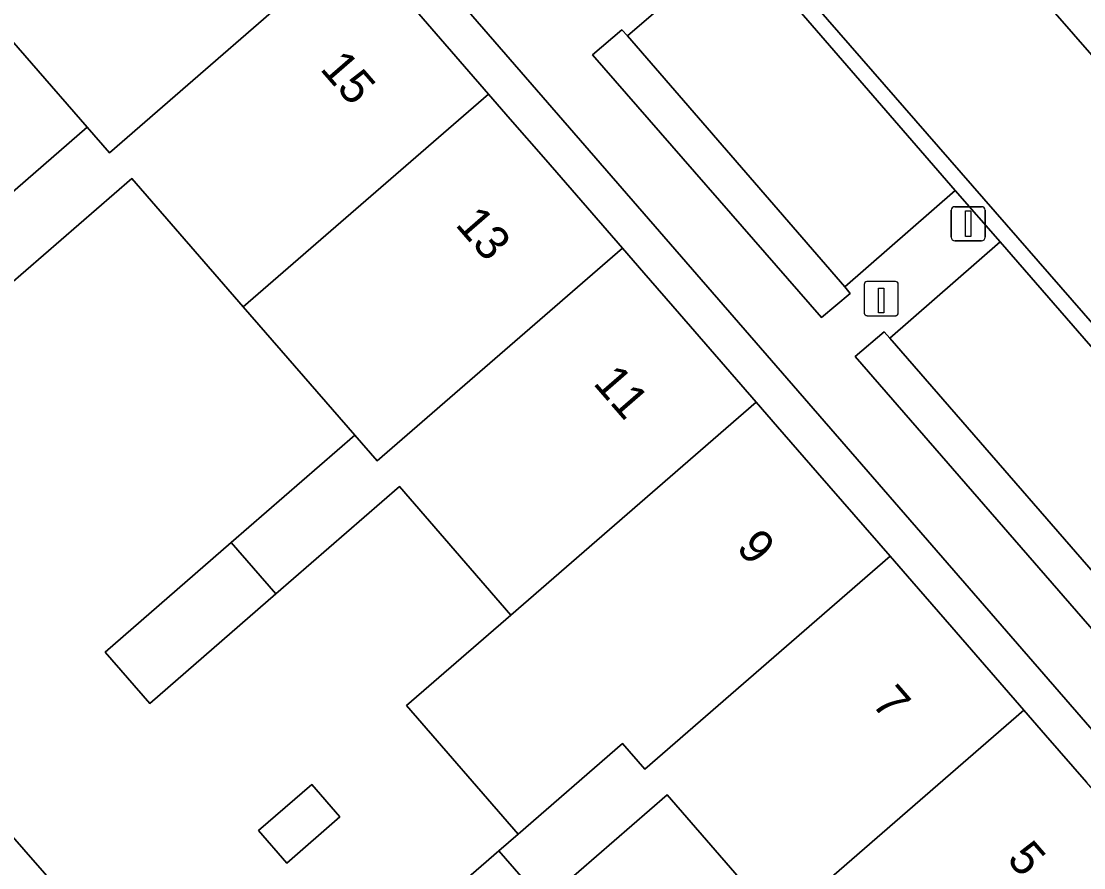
# Model space of a CAD drawing. Extents: x 155887 to 156869, y 383880 to 384678.
# Drawn here: x 156668 to 156699.23, y 384051.97 to 384076.85 of the extents above; entities that cross this region are included whole.
import ezdxf

# ---------------------------------------------------------------- set-up
doc = ezdxf.new("R2010")
doc.units = 0
for name, color, linetype in [('IMGEO_Erf', 7, 'Continuous'), ('IMGEO_Groenvoorziening', 7, 'Continuous'), ('IMGEO_Haag', 7, 'Continuous'), ('IMGEO_Laadpaal', 7, 'Continuous'), ('IMGEO_Lichtmast', 7, 'Continuous'), ('IMGEO_Pand', 7, 'Continuous'), ('IMGEO_Pand_nummerreeks', 7, 'Continuous'), ('IMGEO_Parkeervlak_open', 7, 'Continuous'), ('IMGEO_Rijbaan_lokaal_gesloten', 7, 'Continuous'), ('IMGEO_Rijbaan_lokaal_open', 7, 'Continuous'), ('IMGEO_Voetpad_open', 7, 'Continuous')]:
    doc.layers.add(name, color=color, linetype=linetype)

msp = doc.modelspace()

# ---------------------------------------------------------------- linework, layer by layer
at = {"layer": 'IMGEO_Erf'}
for points in [[(156702.45, 384052.606), (156666.669, 384093.809)], [(156666.303, 384070.582), (156669.934, 384073.737), (156666.655, 384077.511)], [(156679.36, 384077.444), (156681.735, 384074.71), (156682.374, 384073.976), (156683.419, 384072.773), (156685.67, 384070.182), (156686.301, 384069.455), (156687.351, 384068.248), (156689.605, 384065.653), (156690.235, 384064.928), (156691.407, 384063.579), (156693.539, 384061.125), (156694.178, 384060.389), (156695.355, 384059.035), (156697.474, 384056.596), (156698.108, 384055.866), (156699.314, 384054.479)], [(156646.945, 384076.691), (156671.041, 384049.103)], [(156678.337, 384049.248), (156682.042, 384052.467), (156682.604, 384052.955), (156679.326, 384056.734), (156682.394, 384059.396), (156679.115, 384063.17), (156675.484, 384060.015), (156671.779, 384056.795), (156670.467, 384058.305), (156674.173, 384061.524), (156677.804, 384064.679), (156674.525, 384068.453), (156671.246, 384072.227), (156667.615, 384069.072)], [(156690.262, 384050.338), (156686.985, 384054.112), (156683.354, 384050.957)]]:
    msp.add_lwpolyline(points, dxfattribs=at)
msp.add_lwpolyline([(156675.802, 384052.106), (156674.974, 384053.058), (156676.537, 384054.416), (156677.365, 384053.464)], close=True, dxfattribs=at)
at = {"layer": 'IMGEO_Groenvoorziening'}
for points in [[(156685.823, 384076.419), (156685.653, 384076.598), (156684.796, 384075.865), (156691.528, 384068.14), (156692.365, 384068.849), (156692.215, 384069.042)], [(156693.531, 384067.538), (156693.363, 384067.725), (156692.513, 384066.999), (156703.906, 384053.898), (156704.744, 384054.644), (156701.662, 384058.188)]]:
    msp.add_lwpolyline(points, close=True, dxfattribs=at)
at = {"layer": 'IMGEO_Haag'}
for points in [[(156692.215, 384069.042), (156685.823, 384076.419), (156685.653, 384076.598), (156684.796, 384075.865), (156691.528, 384068.14), (156692.365, 384068.849)], [(156701.662, 384058.188), (156693.531, 384067.538), (156693.363, 384067.725), (156692.513, 384066.999), (156703.906, 384053.898), (156704.744, 384054.644)]]:
    msp.add_lwpolyline(points, close=True, dxfattribs=at)
at = {"layer": 'IMGEO_Laadpaal'}
for p, q in [((156692.782, 384069.112), (156692.782, 384068.271)), ((156692.782, 384069.112), (156692.782, 384068.271)), ((156693.698, 384069.196), (156692.857, 384069.196)), ((156693.698, 384069.196), (156692.857, 384069.196)), ((156693.782, 384068.28), (156693.782, 384069.121)), ((156693.782, 384068.28), (156693.782, 384069.121)), ((156692.866, 384068.196), (156693.707, 384068.196)), ((156692.866, 384068.196), (156693.707, 384068.196))]:
    msp.add_line(p, q, dxfattribs=at)
msp.add_lwpolyline([(156693.197, 384069.009), (156693.357, 384069.009), (156693.357, 384068.276), (156693.197, 384068.276), (156693.197, 384069.009)], dxfattribs=at)
for centre, start, end in [((156692.86, 384069.118), 92.4484, 184.2845), ((156692.86, 384069.118), 92.4484, 184.2845), ((156693.704, 384069.118), 2.4484, 94.2845), ((156693.704, 384069.118), 2.4484, 94.2845), ((156692.86, 384068.274), 182.4484, 274.2845), ((156692.86, 384068.274), 182.4484, 274.2845), ((156693.704, 384068.274), 272.4484, 4.2845), ((156693.704, 384068.274), 272.4484, 4.2845)]:
    msp.add_arc(centre, 0.0779, start, end, dxfattribs=at)
at = {"layer": 'IMGEO_Lichtmast'}
for p, q in [((156695.342, 384070.5), (156695.342, 384071.3)), ((156695.342, 384071.3), (156695.342, 384070.5)), ((156695.442, 384071.4), (156696.232, 384071.4)), ((156696.232, 384071.4), (156695.442, 384071.4)), ((156696.332, 384071.3), (156696.332, 384070.5)), ((156696.332, 384070.5), (156696.332, 384071.3)), ((156696.232, 384070.4), (156695.442, 384070.4)), ((156695.442, 384070.4), (156696.232, 384070.4))]:
    msp.add_line(p, q, dxfattribs=at)
msp.add_lwpolyline([(156695.762, 384071.275), (156695.912, 384071.275), (156695.912, 384070.525), (156695.762, 384070.525), (156695.762, 384071.275)], dxfattribs=at)
for centre, start, end in [((156695.442, 384071.3), 90, 180), ((156695.442, 384071.3), 90, 180), ((156696.232, 384071.3), 0, 90), ((156696.232, 384071.3), 360, 90), ((156695.442, 384070.5), 180, 270), ((156695.442, 384070.5), 180, 270), ((156696.232, 384070.5), 270, 0), ((156696.232, 384070.5), 270, 0)]:
    msp.add_arc(centre, 0.1, start, end, dxfattribs=at)
at = {"layer": 'IMGEO_Pand'}
for points in [[(156666.655, 384077.511), (156669.934, 384073.737), (156670.59, 384072.982), (156677.799, 384079.24), (156675.423, 384081.975), (156674.515, 384083.021), (156673.865, 384083.769)], [(156667.615, 384069.072), (156671.246, 384072.227), (156674.525, 384068.453), (156681.735, 384074.71), (156679.36, 384077.444), (156678.447, 384078.495), (156677.799, 384079.24), (156670.59, 384072.982), (156669.934, 384073.737), (156666.303, 384070.582)], [(156685.67, 384070.182), (156683.419, 384072.773), (156682.374, 384073.976), (156681.735, 384074.71), (156674.525, 384068.453), (156677.804, 384064.679), (156678.46, 384063.924)], [(156685.67, 384070.182), (156678.46, 384063.924), (156677.804, 384064.679), (156674.173, 384061.524), (156675.484, 384060.015), (156679.115, 384063.17), (156682.394, 384059.396), (156689.605, 384065.653), (156687.351, 384068.248), (156686.301, 384069.455)], [(156693.539, 384061.125), (156691.407, 384063.579), (156690.235, 384064.928), (156689.605, 384065.653), (156682.394, 384059.396), (156679.326, 384056.734), (156682.604, 384052.955), (156685.673, 384055.622), (156686.329, 384054.867)], [(156675.484, 384060.015), (156674.173, 384061.524), (156670.467, 384058.305), (156671.779, 384056.795)], [(156697.474, 384056.596), (156695.355, 384059.035), (156694.178, 384060.389), (156693.539, 384061.125), (156686.329, 384054.867), (156685.673, 384055.622), (156682.604, 384052.955), (156682.042, 384052.467), (156683.354, 384050.957), (156686.985, 384054.112), (156690.262, 384050.338)], [(156690.262, 384050.338), (156694.362, 384045.615), (156701.592, 384051.857), (156699.314, 384054.479), (156698.108, 384055.866), (156697.474, 384056.596)], [(156675.802, 384052.106), (156677.365, 384053.464), (156676.537, 384054.416), (156674.974, 384053.058)], [(156683.354, 384050.957), (156682.042, 384052.467), (156678.337, 384049.248), (156679.648, 384047.738)]]:
    msp.add_lwpolyline(points, close=True, dxfattribs=at)
at = {"layer": 'IMGEO_Parkeervlak_open'}
for points in [[(156695.457, 384071.872), (156689.082, 384079.232), (156685.823, 384076.419), (156692.215, 384069.042)], [(156696.778, 384070.365), (156693.531, 384067.538), (156701.662, 384058.188), (156704.744, 384054.644), (156706.357, 384056.045), (156707.975, 384057.462), (156706.573, 384059.093), (156704.9, 384061.019)]]:
    msp.add_lwpolyline(points, close=True, dxfattribs=at)
at = {"layer": 'IMGEO_Rijbaan_lokaal_gesloten'}
for points in [[(156707.089, 384059.25), (156688.102, 384081.041), (156680.796, 384089.479), (156662.154, 384110.91), (156634.612, 384142.629)], [(156634.265, 384142.334), (156635.094, 384141.353), (156645.276, 384129.637), (156646.591, 384128.125), (156648.334, 384126.107), (156653.088, 384120.655), (156654.396, 384119.142), (156661.071, 384111.467), (156662.385, 384109.95), (156667.373, 384104.188), (156668.515, 384102.891), (156669.957, 384101.21), (156672.182, 384098.688), (156673.627, 384097.017), (156674.784, 384095.678), (156679.734, 384089.985), (156681.066, 384088.468), (156686.032, 384082.758), (156687.753, 384080.745), (156689.082, 384079.232), (156695.457, 384071.872), (156696.778, 384070.365), (156704.9, 384061.019)]]:
    msp.add_lwpolyline(points, dxfattribs=at)
at = {"layer": 'IMGEO_Rijbaan_lokaal_open'}
msp.add_lwpolyline([(156760.882, 384256.094), (156758.942, 384250.73), (156758.21, 384248.7), (156748.746, 384222.717), (156698.981, 384085.572), (156698.866, 384085.52), (156696.881, 384084.965), (156696.693, 384084.921), (156691.649, 384084.815), (156701.762, 384073.232), (156702.148, 384078.82), (156702.835, 384080.846), (156762.028, 384244.15)], dxfattribs=at)
at = {"layer": 'IMGEO_Voetpad_open'}
for points in [[(156715.884, 384057.159), (156714.376, 384058.642), (156712.098, 384061.075), (156712.256, 384061.212), (156701.762, 384073.232), (156691.649, 384084.815), (156674.809, 384104.102), (156664.299, 384116.202), (156638.481, 384145.993)], [(156634.612, 384142.629), (156662.154, 384110.91), (156680.796, 384089.479), (156688.102, 384081.041), (156707.089, 384059.25), (156708.358, 384057.797), (156710.535, 384055.305), (156710.605, 384055.225)], [(156666.669, 384093.809), (156702.45, 384052.606)], [(156703.906, 384053.898), (156692.513, 384066.999), (156693.363, 384067.725), (156693.531, 384067.538), (156696.778, 384070.365), (156695.457, 384071.872), (156692.215, 384069.042), (156692.365, 384068.849), (156691.528, 384068.14), (156684.796, 384075.865), (156685.653, 384076.598), (156685.823, 384076.419), (156689.082, 384079.232)]]:
    msp.add_lwpolyline(points, dxfattribs=at)
msp.add_lwpolyline([(156646.945, 384076.691), (156645.025, 384075.023), (156674.565, 384041.006), (156674.785, 384041.198), (156676.887, 384038.78), (156676.665, 384038.587), (156677.751, 384037.337), (156680.639, 384034.016), (156680.803, 384033.827), (156682.932, 384035.678), (156682.767, 384035.867), (156679.879, 384039.187), (156674.64, 384044.933), (156671.041, 384049.103)], close=True, dxfattribs=at)

# ---------------------------------------------------------------- texts
at = {"layer": 'IMGEO_Pand_nummerreeks'}
for s, rotation, p in [('15', 310.9865, (156676.756, 384075.441)), ('13', 310.9865, (156680.733, 384070.863)), ('11', 310.9865, (156684.786, 384066.199)), ('9', 310.9892, (156688.991, 384061.36)), ('7', 310.9892, (156692.969, 384056.781)), ('5', 310.9865, (156696.947, 384052.202))]:
    msp.add_text(s, height=1, rotation=rotation, dxfattribs=at).set_placement(p)

doc.saveas('drawing.dxf')
